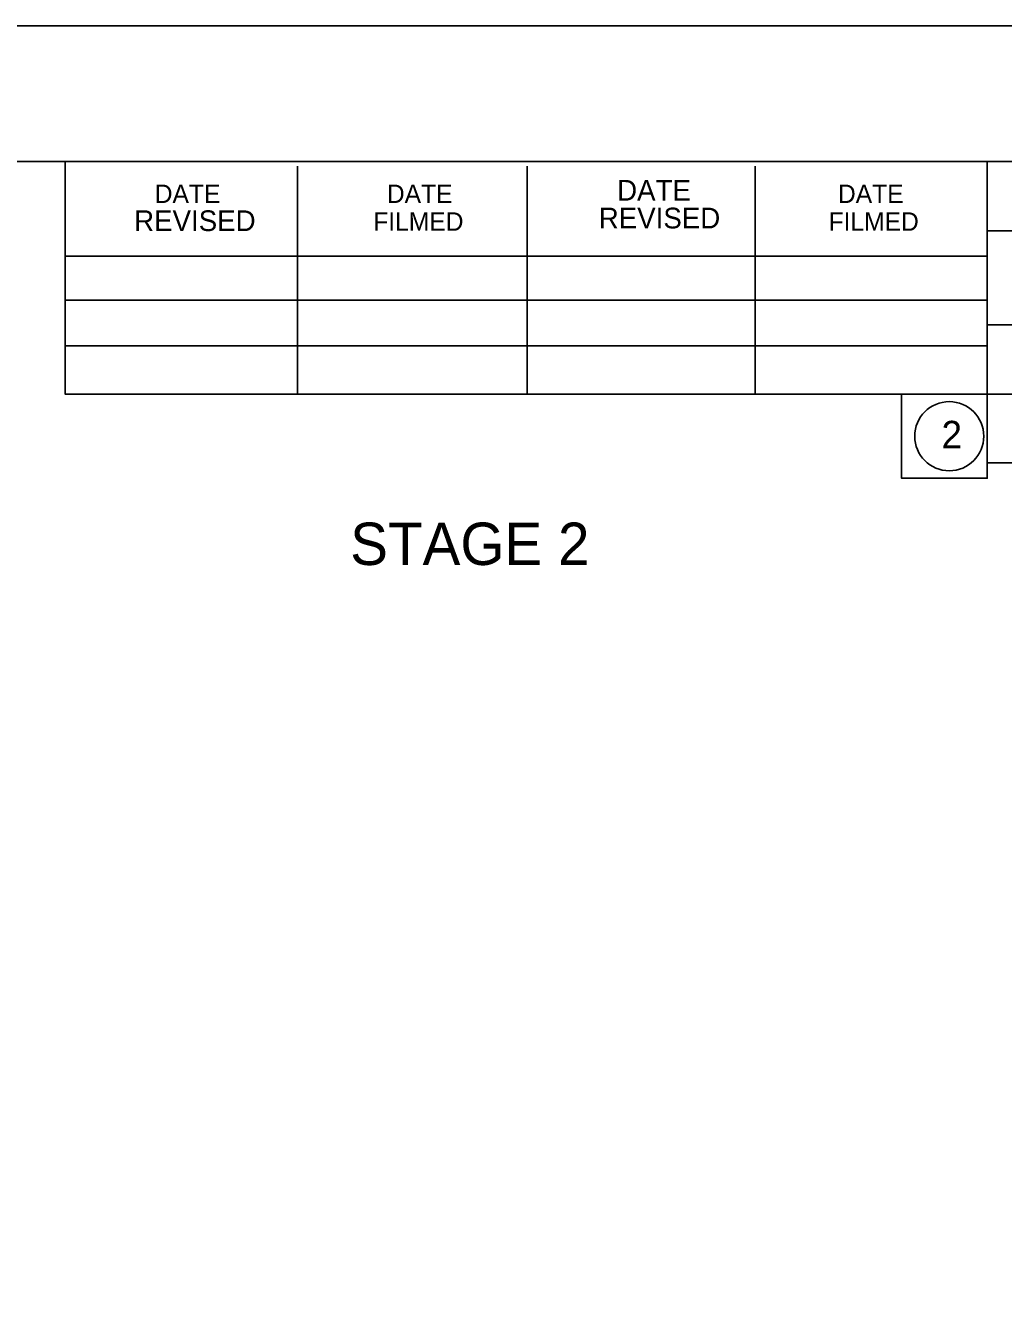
# Model space of a CAD drawing. Extents: x 0 to 1228740, y 0 to 152440.
# Drawn here: x 25.03 to 29.18, y 16.55 to 22 of the extents above; entities that cross this region are included whole.
import ezdxf

# ---------------------------------------------------------------- set-up
doc = ezdxf.new("R2010")
doc.units = 0
for name, color, linetype in [('R_Border', 7, 'Continuous'), ('R_No Plot', 7, 'Continuous'), ('R_XS_EARTHWORK_STAGE2', 7, 'Continuous')]:
    doc.layers.add(name, color=color, linetype=linetype)

msp = doc.modelspace()

# ---------------------------------------------------------------- linework, layer by layer
at = {"layer": 'R_Border'}
for p, q in [((1.516, 21.4232), (33.4231, 21.4232)), ((25.1971, 20.4352), (25.1971, 21.4232)), ((26.1831, 20.4352), (26.1831, 21.4032)), ((27.1591, 20.4352), (27.1591, 21.4032)), ((28.1271, 20.4352), (28.1271, 21.4032)), ((29.1131, 21.4232), (29.1131, 20.1432)), ((33.4231, 21.1292), (29.1131, 21.1292)), ((25.1971, 21.0212), (29.1131, 21.0212)), ((25.1971, 20.8352), (29.1131, 20.8352)), ((33.4231, 20.7292), (29.1131, 20.7292)), ((25.1971, 20.4352), (25.1971, 20.6412)), ((25.1971, 20.6412), (29.1131, 20.6412)), ((33.4231, 20.4352), (25.1971, 20.4352)), ((29.1131, 20.1432), (33.4231, 20.1432))]:
    msp.add_line(p, q, dxfattribs=at)
msp.add_lwpolyline([(34, 22), (0, 22), (0, 0), (34, 0)], close=True, dxfattribs=at)
msp.add_circle((28.9518, 20.2569), 0.1467, dxfattribs=at)
at = {"layer": 'R_No Plot'}
for points in [[(33.4231, 17.4052), (33.4231, 10.8708), (1.516, 10.8708), (1.516, 21.4232), (25.1971, 21.4232), (25.1971, 20.4352), (28.7491, 20.4352), (28.7491, 20.0782), (29.1131, 20.0782), (29.1131, 20.1432), (30.6665, 20.1432)], [(33.4231, 17.4052), (33.4231, 0.6568), (1.516, 0.6568), (1.516, 21.4232), (25.1971, 21.4232), (25.1971, 20.4352), (28.7491, 20.4352), (28.7491, 20.0782), (29.1131, 20.0782), (29.1131, 20.1432), (30.6665, 20.1432)]]:
    msp.add_lwpolyline(points, dxfattribs=at)

# ---------------------------------------------------------------- texts
at = {"layer": 'R_Border'}
for s, height, p in [('DATE', 0.08792, (27.5409, 21.2572)), ('DATE', 0.07819, (25.5769, 21.2472)), ('DATE', 0.07819, (26.5629, 21.2472)), ('DATE', 0.07819, (28.4789, 21.2472)), ('REVISED', 0.08792, (27.4629, 21.1392)), ('REVISED', 0.08792, (25.4893, 21.1279)), ('FILMED', 0.07819, (26.5049, 21.1292)), ('FILMED', 0.07819, (28.4389, 21.1292)), ('2', 0.1172, (28.9189, 20.2049))]:
    msp.add_text(s, height=height, dxfattribs=at).set_placement(p)
at = {"layer": 'R_XS_EARTHWORK_STAGE2'}
msp.add_text('STAGE 2', height=0.18, dxfattribs=at).set_placement((26.407, 19.71))

doc.saveas('drawing.dxf')
